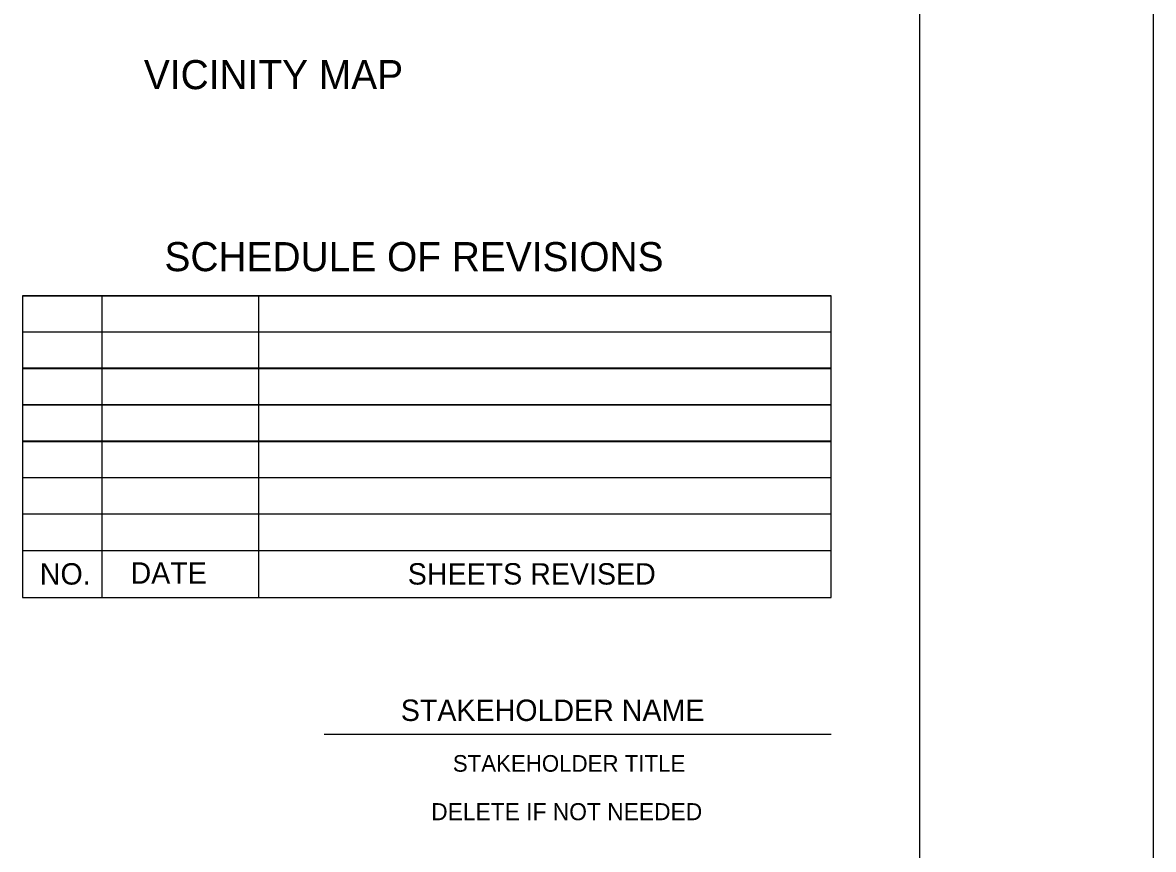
# Model space of a CAD drawing. Extents: x 0.19 to 2.82, y 0.04 to 1.79.
# Drawn here: x 2.253 to 2.817, y 0.949 to 1.361 of the extents above; entities that cross this region are included whole.
import ezdxf

# ---------------------------------------------------------------- set-up
doc = ezdxf.new("R2010")
doc.units = 0
for name, color, linetype in [('Annotation', 7, 'Continuous'), ('Stamp', 7, 'Continuous'), ('Standard Info', 7, 'Continuous')]:
    doc.layers.add(name, color=color, linetype=linetype)

msp = doc.modelspace()

# ---------------------------------------------------------------- linework, layer by layer
at = {"layer": 'Annotation'}
msp.add_lwpolyline([(2.7, 0.04167), (2.81667, 0.04167), (2.81667, 1.79166), (2.7, 1.79166)], close=True, dxfattribs=at)
at = {"layer": 'Standard Info'}
for p, q in [((2.25276, 1.22523), (2.65594, 1.22523)), ((2.29249, 1.07498), (2.29249, 1.22523)), ((2.37051, 1.07498), (2.37051, 1.22523)), ((2.65145, 1.22551), (2.65594, 1.22551)), ((2.65594, 1.07498), (2.65594, 1.22523)), ((2.29249, 1.11111), (2.29249, 1.21286)), ((2.37051, 1.11111), (2.37051, 1.21286)), ((2.25276, 1.20731), (2.65594, 1.20731)), ((2.65145, 1.20731), (2.65594, 1.20731)), ((2.25276, 1.18938), (2.65594, 1.18938)), ((2.25276, 1.18911), (2.65594, 1.18911)), ((2.65145, 1.18938), (2.65594, 1.18938)), ((2.25276, 1.17118), (2.65594, 1.17118)), ((2.25276, 1.17091), (2.65594, 1.17091)), ((2.65145, 1.17118), (2.65594, 1.17118)), ((2.65145, 1.17091), (2.65594, 1.17091)), ((2.25276, 1.15298), (2.65594, 1.15298)), ((2.25276, 1.15271), (2.65594, 1.15271)), ((2.65145, 1.15271), (2.65594, 1.15271)), ((2.25276, 1.13478), (2.65594, 1.13478)), ((2.65145, 1.13478), (2.65594, 1.13478)), ((2.25276, 1.11658), (2.65594, 1.11658)), ((2.65145, 1.11658), (2.65594, 1.11658)), ((2.25276, 1.09838), (2.65594, 1.09838)), ((2.65145, 1.09838), (2.65594, 1.09838)), ((2.25276, 1.07498), (2.29249, 1.07498)), ((2.65145, 1.07498), (2.65594, 1.07498)), ((2.40311, 1.00675), (2.65594, 1.00675))]:
    msp.add_line(p, q, dxfattribs=at)
msp.add_lwpolyline([(2.65594, 1.22523), (2.25276, 1.22523), (2.25276, 1.07498), (2.65594, 1.07498)], dxfattribs=at)

# ---------------------------------------------------------------- texts
at = {"layer": 'Stamp'}
msp.add_text('DELETE IF NOT NEEDED', height=0.0085, dxfattribs=at).set_placement((2.45651, 0.96388))
at = {"layer": 'Standard Info'}
for s, height, p in [('VICINITY MAP', 0.0145, (2.31323, 1.32831)), ('SCHEDULE OF REVISIONS', 0.0145, (2.3235, 1.23757)), ('NO.', 0.01067, (2.26133, 1.08134)), ('DATE', 0.01067, (2.30659, 1.08178)), ('SHEETS REVISED', 0.01067, (2.44482, 1.08134)), ('STAKEHOLDER NAME', 0.01067, (2.44136, 1.01335)), ('STAKEHOLDER TITLE', 0.0083, (2.4673, 0.98805))]:
    msp.add_text(s, height=height, dxfattribs=at).set_placement(p)

doc.saveas('drawing.dxf')
